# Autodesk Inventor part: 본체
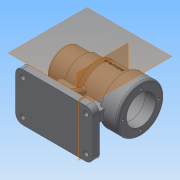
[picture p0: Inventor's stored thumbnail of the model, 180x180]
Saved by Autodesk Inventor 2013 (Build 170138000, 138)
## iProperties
Created: 2016-06
Part Number: 본체
Material: 일반
Document SubType Name: Modeling
Designer: Administrator
Mass: 670.414 g
Surface Area: 631.805 cm^2
Volume: 247.385 cm^3
Density: 1 g/cm^3
Author: Administrator
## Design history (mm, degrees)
sketch "스케치1"
  geometry: L1 (-35, -70)-(35, -70); L2 (-35, -70)-(-35, -60); L3 (-35, -60)-(35, -60); L4 (35, -60)-(35, -70); L5 (43.243, 5.419)-(-43.243, 5.419); L6 (72.217, 26.419)-(57.217, 26.419); L7 (57.217, 26.419)-(57.217, 29.419); L8 (57.217, 29.419)-(3.217, 29.419); L9 (3.217, 29.419)-(3.217, 22.919); L10 (3.217, 22.919)-(-8.783, 22.919); L11 (-8.783, 22.919)-(-8.783, 21.419); L12 (-8.783, 21.419)-(-26.783, 21.419); L13 (-26.783, 21.419)-(-26.783, 15.919); L14 (-39.783, 5.419)-(-39.783, 30.419); L15 (-39.783, 30.419)-(-14.783, 30.419); L16 (-14.783, 30.419)-(-14.783, 32.419); L17 (-14.783, 32.419)-(5.217, 32.419); L18 (5.217, 32.419)-(5.217, 35.419); L19 (5.217, 35.419)-(44.217, 35.419); L20 (44.217, 35.419)-(44.217, 39.419); L21 (44.217, 39.419)-(72.217, 39.419); L22 (72.217, 26.419)-(72.217, 39.419); L23 (-26.783, 15.919)-(-29.605, 15.919); L24 (-29.605, 15.919)-(-29.605, 5.419); L25 (-29.605, 5.419)-(-39.783, 5.419); 3 further points
  constraints: 50 end point, 6 perpendicular, 4 parallel, 2 midpoint, 2 vertical alignment, 1 collinear, 1 horizontal, 1 point on line
  dimensions: "d0" = 70 distance of point (0, 0) point (0, -70); "d1" = 70 distance of L1.start L1.end; "d2" = 10 distance of L1.start L2.end; "d8" = 48 diameter of L7.end L5; "d9" = 35 diameter of L9.end L5; "d11" = 32 diameter of L11.end L5; "d12" = 21 diameter of L13.end L5; "d14" = 18 distance of L11.end L12.end; "d15" = 12 distance of L9.end L10.end; "d16" = 54 distance of L7.end L8.end; "d20" = 42 diameter of L6.start L5; "d22" = 68 diameter of L21.end L5; "d23" = 15 distance of L6.start L6.end; "d24" = 50 diameter of L14.end L5; "d25" = 25 distance of L14.end L15.end; "d26" = 54 diameter of L16.end L5; "d27" = 20 distance of L16.end L17.end; "d28" = 60 diameter of L18.end L5; "d29" = 39 distance of L18.end L19.end; "d30" = 28 distance of L20.end L21.end; "d31" = 21 diameter of L23.end L5 (derived)
revolve "회전1" sketch "스케치1" stored, may be unused: angle "d32" = 90 deg
node "작업 평면1"
sketch "스케치3"
  geometry: L1 (-35, -60)-(35, -60); L2 (35, -60)-(35, -70); L3 (35, -70)-(-35, -70); L4 (-35, -70)-(-35, -60); C1 r 34 at (0, 0) reference; 2 further points
  constraints: 8 end point, 2 parallel, 1 horizontal, 1 midpoint, 1 perpendicular, 1 vertical alignment
  dimensions: "d34" = 70 distance of L2.end L3.end; "d36" = 10 distance of L1.end L2.end; "d37" = 70 distance from line of L3 C1.centre
extrude "돌출1" join sketch "스케치3" stored distance "d38" = 112; taper "d39" = 0 deg
node "작업 평면2"
sketch "스케치4"
  geometry: L1 (-35, -60)-(35, -60) reference; L2 (-35, -70)-(-35, -60) reference; L3 (35, -70)-(-35, -70) reference; L4 (-12.807, -27.129)-(-25, -60); L5 (14.287, -26.379)-(25, -60); L6 (25, -60)-(0, -60); L7 (0, -30)-(0, -60); L8 (0, -30)-(14.287, -26.379); A1 r 30 centre (0, 0) between (-12.807, -27.129) and (14.287, -26.379) reference; 1 further point
  constraints: 10 end point, 3 point on circle, 2 coincident, 2 point on line, 1 midpoint, 1 perpendicular
  dimensions: "d43" = 25 horizontal distance of L4.end A1.centre; "d44" = 25 horizontal distance of L5.end A1.centre
extrude "돌출2" join sketch "스케치4" stored distance "d45" = 10; taper "d46" = 0 deg
sketch "스케치5"
  geometry: L1 (0, -29.949)-(-12.744, -27.297); 1 further point
  constraints: 2 end point
extrude "돌출3" join sketch "스케치4" stored distance "d47" = 10; taper "d48" = 0 deg
node "작업 평면3"
sketch "스케치6"
  geometry: L1 (0, 0)-(112, 0) reference; L2 (0, -10)-(0, 0) reference; L3 (0, -10)-(112, -10) reference; L4 (112, 0)-(112, -10) reference; 1 further point
sketch "스케치7"
  geometry: L1 (-35, -60)-(35, -60) reference; L2 (-35, -70)-(-35, -60) reference; L3 (35, -70)-(-35, -70) reference; L4 (-25, -60)-(25, -60) reference; L5 (0, -60)-(-4, -60); L6 (-4, -60)-(-4, -25.072); L7 (-4, -25.072)-(0, -25.072); L8 (0, -25.072)-(0, -60); L9 (0, -60)-(4, -60); L10 (4, -60)-(4, -25.072); L11 (4, -25.072)-(0, -25.072); L12 (0, -25.072)-(0, -60); 1 further point
  constraints: 16 end point, 4 parallel, 2 horizontal, 2 perpendicular, 1 midpoint
  dimensions: "d50" = 35 distance of L1.start L5.start (derived); "d51" = 4 distance of L6.end L7.end; "d52" = 4 distance of L11.end L10.end
sketch "스케치8"
  geometry: C1 r 21 at (0, 0) reference; C2 r 34 at (0, 0) reference; C3 r 26 at (0, 0); 2 further points
  constraints: 1 centre point, 1 coincident, 1 vertical alignment
  dimensions: "d53" = 52 diameter of C3; "d55" = 26 distance of C1.centre point (0, 26)
hole "구멍1" sketch "스케치8" at (0, 26) diameter "d56" = 3.459; stored, may be unused: countersink angle "d60" = 90 deg, drill point angle "d62" = 118 deg; dims "d57" = 8, "d58" = 4, "d59" = 2, "d61" = 11
sketch "스케치9"
  geometry: L1 (112, 70)-(112, 0) reference; L2 (112, 70)-(0, 70) reference; 2 further points
  dimensions: "d66" = 10 distance from line of L1 point (102, 60); "d67" = 10 distance from line of L2 point (102, 60)
fillet "모깎기1" dims "d68" = 10
sketch "스케치10"
  geometry: A1 r 10 centre (92, 10) between (92, 0) and (102, 10) reference; 1 further point
hole "구멍2" sketch "스케치9" diameter "d69" = 7; stored, may be unused: countersink angle "d73" = 90 deg, drill point angle "d75" = 0 deg; dims "d70" = 8, "d71" = 4, "d72" = 2, "d74" = 10
hole "구멍3" sketch "스케치10" diameter "d76" = 7; stored, may be unused: countersink angle "d80" = 90 deg, drill point angle "d82" = 0 deg; dims "d77" = 8, "d78" = 4, "d79" = 2, "d81" = 10
sketch "스케치11"
  geometry: A1 r 10 centre (0, 60) between (0, 70) and (-10, 60) reference; 1 further point
hole "구멍4" sketch "스케치11" at (0, 60) diameter "d83" = 7; stored, may be unused: countersink angle "d87" = 90 deg, drill point angle "d89" = 0 deg; dims "d84" = 8, "d85" = 4, "d86" = 2, "d88" = 10
sketch "스케치12"
  geometry: A1 r 10 centre (0, 10) between (-10, 10) and (0, 0) reference; 1 further point
hole "구멍5" sketch "스케치12" at (0, 10) diameter "d90" = 7; stored, may be unused: countersink angle "d94" = 90 deg, drill point angle "d96" = 0 deg; dims "d91" = 8, "d92" = 4, "d93" = 2, "d95" = 10
fillet "모깎기2" dims "d97" = 3
node "작업 평면4"
sketch "스케치13"
  geometry: 2 further points
  constraints: 1 other
feature "엠보싱1" sketch "스케치13" dims "d0" = 70, "d1" = 70, "d2" = 10, "d8" = 48, "d9" = 35, "d11" = 32, "d12" = 21, "d14" = 18, "d15" = 12, "d16" = 54, "d20" = 42, "d22" = 68, "d23" = 15, "d24" = 50, "d25" = 25, "d26" = 54, "d27" = 20, "d28" = 60, "d29" = 39, "d30" = 28, "d31" = 21 (derived), "d99" = 0.5, "d100" = 0
sketch "스케치14"
  geometry: L1 (-8, -25.943)-(8, -25.943); L2 (8, -25.943)-(8, -65.377); L3 (8, -65.377)-(-8, -65.377); L4 (-8, -65.377)-(-8, -25.943); 1 further point
  constraints: 8 end point, 2 parallel, 1 horizontal, 1 perpendicular
  dimensions: "d101" = 8 distance from line of point (0, -5.419) L4; "d102" = 16 distance of L2.end L3.end
extrude "돌출4" join sketch "스케치14" distance "d103" = 72; taper "d104" = 0 deg
fillet "모깎기3" dims "d105" = 3
node "솔리드1"
pattern_circular "원형 패턴1" dims angle "d64" = 360 deg
other parameters: "d33" = -56, "d40" = -56
